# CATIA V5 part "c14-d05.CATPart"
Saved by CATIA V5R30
Part number: Part1
Bounding box of the stored display mesh (mm): x -55 to 55, y -96.632 to 96.632, z -25 to 65
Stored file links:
  D:\PROJECTS\CATIA V56R 2020\Resources\Parts File\c14_catia_v5_6r2020_prt\c14-catia-v5-6r2020-figr-14-18\c14-d05.CATPart
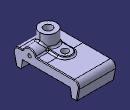
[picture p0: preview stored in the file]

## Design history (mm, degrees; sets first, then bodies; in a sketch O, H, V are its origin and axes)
Body1 (main body)
  Sketch1 on yz-plane, origin (0, 0, 0), H (0, 0, -1), V (0, 1, 0)
    construction line L1 (-49.4514, 0) -> (56.6299, 0)
    line L2 (0, 0) -> (0, 70.5918)
    point P3 (25, 75)
    line L3 (25, 75) -> (25, 90)
    point P4 (25, 90)
    line L4 (25, 90) -> (-25, 100)
    point P5 (-25, 100)
    line L5 (-25, 100) -> (-25, 0)
    point P6 (-25, 0)
    point P7 (0, 0)
    construction line L6 through (0, 0) direction (-1, 0)
    point P10 (25, -75)
    point P11 (25, -90)
    point P12 (-25, -100)
    point P13 (-25, 0)
    line L7 (0, 0) -> (0, -70.5918)
    line L8 (25, -75) -> (25, -90)
    line L9 (25, -90) -> (-25, -100)
    line L10 (-25, -100) -> (-25, 0)
    line L11 (25, 75) -> (0, 70.5918)
    point P14 (0, 70.5918)
    point P15 (0, -70.5918)
    point P16 (25, -75)
    line L12 (25, -75) -> (0, -70.5918)
    axis line L13 (25, 75) -> (-31.7388, 75)
    distance P5 P12 = 200
    length L3 = 15
    angle L11 L13 = 10
    distance L3 L5 = 50
    distance P3 P10 = 150
    angle L5 L6 = 270 (reference)
    coincidence: P6 L1, O P7, P6 P13, P10 P16
    symmetry: O P7 L1, P3 P10 L1, P4 P11 L1, P5 P12 L1, P6 P13 L1, L2 L7 L1, L3 L8 L1, L4 L9 L1, L5 L10 L1, P14 P15 L1, P3 P16 L1, L11 L12 L1
  Pad1: profile Sketch1, direction (1, 0, 0), length 55, mirrored extent
  Sketch2 on face of Pad1, origin (55, 0, 0), H (0, 1, 0), V (0, 0, 1)
    arc A1 centre (-50, 20) radius 20 from (-30.6351, 25) to (-69.3649, 25) ccw
    point P1 (-50, 20)
    line L1 (-69.3649, 25) -> (-30.6351, 25)
    reference projected line E1 (0, 25) -> (-100, 25) from edge [face of Pad1 | face of Pad1]
    reference projected point E2 (-100, 25) from vertex [face of Pad1 | face of Pad1 | face of Pad1]
    reference projected line E3 (0, 25) -> (-100, 25) from edge [face of Pad1 | face of Pad1]
    radius A1 = 20
    distance P1 E2 H = 50
    distance P1 E3 = 5
    horizontal: L1 H
    coincidence: L1 E1
  Pad2: profile Sketch2, direction (-1, 0, 0), length 55
  Sketch3 on face of Pad1, origin (0, 0, 25), H (1, 0, 0), V (0, 1, 0)
    circle A1 centre (0, -50) radius 25
    point P1 (0, -50)
    point P2 (0, -25)
    radius A1 = 25
    distance P1 H = 50
    coincidence: P1 V, A1 P2, P2 V
  Pad3: profile Sketch3, direction (0, 0, 1), length 40
  Sketch4 on face of Pad1, origin (0, 0, 25), H (1, 0, 0), V (0, 1, 0)
    line L1 (-20, -50) -> (-20, 0)
    point P2 (-20, 0)
    arc A1 centre (0, 0) radius 20 from (-20, 0) to (20, 0) cw
    point P3 (0, 0)
    line L2 (20, 0) -> (20, -50)
    line L3 (20, -50) -> (-20, -50)
    distance P3 L3 = 50
    radius A1 = 20
    coincidence: P2 H, P3 O
    vertical: L1 V, L2 V
    tangency: A1 L1, L2 A1
    horizontal: L3 H
  Pad4: profile Sketch4, direction (0, 0, 1), length 5
  Fillet1: radius 15, on edge [face of Pad1 | face of Pad1] (x2)
  Fillet2: radius 5, on edge [face of Pad1 | face of Pad4]
  Fillet3: radius 2, on edge [face of Pad4 | face of Fillet2]
  Fillet4: radius 5, on edge [face of Pad1 | face of Pad2]
  Fillet5: radius 5, on edge [face of Pad2 | face of Pad1]
  Fillet6: radius 5, on edge [face of Pad2 | face of Pad3]
  Fillet7: radius 2, on edge [face of Pad1 | face of Fillet1]; 1 edge
  Sketch5 on face of Pad1, origin (55, -45.7053, 34.0838), H (0, 1, 0), V (0, 0, 1)
    point P1 (-4.2947, -14.0838)
    reference projected arc E1 centre (-4.2947, -14.0838) radius 20 from (15.0702, -9.0838) to (-23.6596, -9.0838) ccw from edge of Pad2
    concentricity: P1 E1
  Hole1: placed by Sketch5, at (55, -50, 20) direction (-1, 0, 0), diameter 10, depth 20
  Sketch6 on face of Pad3, origin (0, -50, 65), H (1, 0, 0), V (0, 1, 0)
    point P1 (0, 0)
    reference projected circle E1 centre (0, 0) radius 25 from edge [face of Pad3 | face of Pad3]
    concentricity: P1 E1
  Hole2: placed by Sketch6, at (0, -50, 65) direction (0, 0, -1), diameter 25, through (limit type 3)
  Sketch7 on face of Pad4, origin (-2.136, -9.3115, 30), H (1, 0, 0), V (0, 1, 0)
    point P1 (2.136, 9.3115)
    reference projected arc E1 centre (2.136, 9.3115) radius 18.2918 from (20.4278, 9.3115) to (-16.1558, 9.3115) ccw from edge [face of Pad4 | face of Fillet3]
    concentricity: P1 E1
  Hole3: placed by Sketch7, at (0, 0, 30) direction (0, 0, -1), diameter 20, through (limit type 3)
